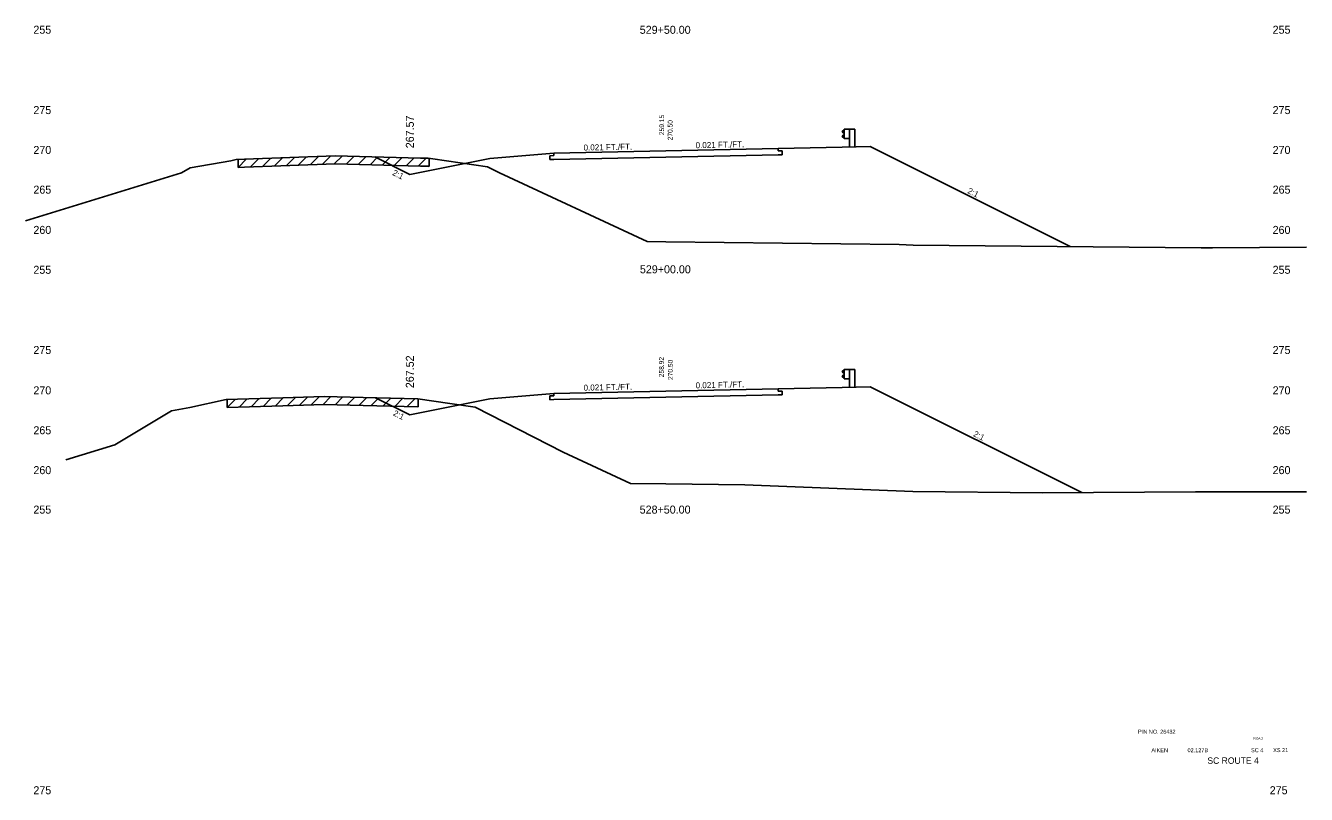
# Model space of a CAD drawing. Extents: x 883 to 1160, y 1002 to 4323.
# Drawn here: x 1000 to 1160, y 3395.1 to 3491.2 of the extents above; entities that cross this region are included whole.
import ezdxf

# ---------------------------------------------------------------- set-up
doc = ezdxf.new("R2010")
doc.units = 0
for name, color, linetype in [('Level 1', 7, 'Continuous'), ('Level 10', 7, 'Continuous'), ('Level 11', 7, 'Continuous'), ('Level 12', 7, 'Continuous'), ('Level 24', 7, 'Continuous'), ('Level 3', 7, 'Continuous'), ('Level 32', 7, 'Continuous'), ('Level 33', 7, 'Continuous'), ('Level 59', 7, 'Continuous'), ('Level 6', 7, 'Continuous'), ('Level 60', 7, 'Continuous'), ('Level 61', 7, 'Continuous'), ('Level 7', 7, 'Continuous')]:
    doc.layers.add(name, color=color, linetype=linetype)

msp = doc.modelspace()

# ---------------------------------------------------------------- linework, layer by layer
at = {"layer": 'Level 11'}
for p, q in [((1066, 3475.21), (1066, 3474.91)), ((1094, 3475.49), (1094, 3475.79)), ((1094.5, 3475.5), (1094, 3475.49)), ((1094.5, 3475.02), (1094.5, 3475.5)), ((1066, 3474.91), (1065.5, 3474.9)), ((1065.5, 3474.9), (1065.5, 3474.42)), ((1065.5, 3474.42), (1066, 3474.43)), ((1094, 3475.01), (1094.5, 3475.02)), ((1066, 3444.91), (1065.5, 3444.9)), ((1065.5, 3444.9), (1065.5, 3444.42)), ((1066, 3445.21), (1066, 3444.91)), ((1094, 3445.49), (1094, 3445.79)), ((1094.5, 3445.5), (1094, 3445.49)), ((1094, 3445.01), (1094.5, 3445.02)), ((1094.5, 3445.02), (1094.5, 3445.5)), ((1065.5, 3444.42), (1066, 3444.43))]:
    msp.add_line(p, q, dxfattribs=at)
at = {"layer": 'Level 12'}
for p, q in [((1080, 3474.72), (1066, 3474.43)), ((1094, 3475.01), (1080, 3474.72)), ((1094, 3445.01), (1080, 3444.72)), ((1080, 3444.72), (1066, 3444.43))]:
    msp.add_line(p, q, dxfattribs=at)
at = {"layer": 'Level 24'}
for p, q in [((1102.27, 3478.13), (1102, 3477.93)), ((1102, 3477.93), (1102, 3477.88)), ((1102, 3477.88), (1102.27, 3477.68)), ((1102, 3477.36), (1102.27, 3477.56)), ((1102, 3477.31), (1102, 3477.36)), ((1102.27, 3477.11), (1102, 3477.31)), ((1102.27, 3477.04), (1102.27, 3478.21)), ((1102.27, 3478.21), (1102.94, 3478.21)), ((1102.27, 3477.04), (1102.94, 3477.04)), ((1102.94, 3478.21), (1102.94, 3475.98)), ((1102.94, 3478.21), (1103.6, 3478.21)), ((1103.6, 3478.21), (1103.6, 3475.99)), ((1102.27, 3448.13), (1102, 3447.93)), ((1102.27, 3447.04), (1102.27, 3448.21)), ((1102.27, 3448.21), (1102.94, 3448.21)), ((1102.94, 3448.21), (1102.94, 3445.98)), ((1102.94, 3448.21), (1103.6, 3448.21)), ((1103.6, 3448.21), (1103.6, 3445.99)), ((1102, 3447.93), (1102, 3447.88)), ((1102, 3447.88), (1102.27, 3447.68)), ((1102, 3447.36), (1102.27, 3447.56)), ((1102, 3447.31), (1102, 3447.36)), ((1102.27, 3447.11), (1102, 3447.31)), ((1102.27, 3447.04), (1102.94, 3447.04))]:
    msp.add_line(p, q, dxfattribs=at)
at = {"layer": 'Level 59'}
for p, q in [((1066, 3475.21), (1080, 3475.5)), ((1080, 3475.5), (1094, 3475.79)), ((1066, 3445.21), (1080, 3445.5)), ((1080, 3445.5), (1094, 3445.79))]:
    msp.add_line(p, q, dxfattribs=at)
at = {"layer": 'Level 6'}
for p, q in [((1058, 3474.54), (1066, 3475.21)), ((1094, 3475.79), (1102, 3475.96)), ((1102, 3475.96), (1105.5, 3476.03)), ((1058, 3444.54), (1066, 3445.21)), ((1094, 3445.79), (1102, 3445.96)), ((1102, 3445.96), (1105.5, 3446.03))]:
    msp.add_line(p, q, dxfattribs=at)
at = {"layer": 'Level 60'}
for p, q in [((1020.56, 3473.4), (1025.63, 3474.28)), ((1025.63, 3474.28), (1026.3, 3474.42)), ((1026.3, 3474.42), (1027.35, 3474.45)), ((1027.35, 3474.45), (1038.67, 3474.87)), ((1038.67, 3474.87), (1049.34, 3474.61)), ((1049.34, 3474.61), (1050.29, 3474.58)), ((1050.29, 3474.58), (1050.86, 3474.5)), ((1050.86, 3474.5), (1057.71, 3473.51)), ((1000, 3466.75), (1019.46, 3472.74)), ((1019.46, 3472.74), (1020.56, 3473.4)), ((1057.71, 3473.51), (1059.19, 3472.76)), ((1059.19, 3472.76), (1077.65, 3464.18)), ((1077.65, 3464.18), (1080, 3464.15)), ((1080, 3464.15), (1109.11, 3463.81)), ((1109.11, 3463.81), (1110.87, 3463.74)), ((1110.87, 3463.74), (1146.86, 3463.38)), ((1146.86, 3463.38), (1147.74, 3463.39)), ((1147.74, 3463.39), (1148.26, 3463.39)), ((1148.26, 3463.39), (1160, 3463.46)), ((1032.14, 3444.64), (1037.31, 3444.83)), ((1037.31, 3444.83), (1042.18, 3444.71)), ((1018.22, 3443.04), (1020.51, 3443.44)), ((1020.51, 3443.44), (1025.07, 3444.43)), ((1025.07, 3444.43), (1032.14, 3444.64)), ((1042.18, 3444.71), (1048.98, 3444.54)), ((1048.98, 3444.54), (1053.01, 3443.96)), ((1053.01, 3443.96), (1056.15, 3443.5)), ((1056.15, 3443.5), (1067.15, 3437.88)), ((1011.14, 3438.8), (1018.22, 3443.04)), ((1005.03, 3436.92), (1011.14, 3438.8)), ((1067.15, 3437.88), (1075.57, 3433.97)), ((1075.57, 3433.97), (1080, 3433.92)), ((1080, 3433.92), (1089.85, 3433.8)), ((1089.85, 3433.8), (1110.85, 3432.95)), ((1110.85, 3432.95), (1127.05, 3432.79)), ((1127.05, 3432.79), (1146.13, 3432.9)), ((1146.13, 3432.9), (1157.43, 3432.9)), ((1157.43, 3432.9), (1160, 3432.91))]:
    msp.add_line(p, q, dxfattribs=at)
at = {"layer": 'Level 61'}
for p, q in [((1027.57, 3474.46), (1026.54, 3473.43)), ((1026.54, 3474.43), (1026.54, 3473.43)), ((1027.35, 3473.45), (1038.67, 3473.87)), ((1029.08, 3474.52), (1028.04, 3473.48)), ((1030.58, 3474.57), (1029.54, 3473.53)), ((1032.08, 3474.63), (1031.04, 3473.59)), ((1033.58, 3474.68), (1032.54, 3473.64)), ((1035.08, 3474.74), (1034.04, 3473.7)), ((1036.58, 3474.79), (1035.55, 3473.76)), ((1038.09, 3474.85), (1037.05, 3473.81)), ((1039.53, 3474.85), (1038.55, 3473.87)), ((1038.67, 3473.87), (1049.34, 3473.61)), ((1041.02, 3474.81), (1040.05, 3473.84)), ((1042.52, 3474.78), (1041.55, 3473.8)), ((1044.02, 3474.74), (1043.05, 3473.76)), ((1045.53, 3474.7), (1044.55, 3473.73)), ((1047.03, 3474.66), (1046.05, 3473.69)), ((1048.53, 3474.63), (1047.55, 3473.65)), ((1050.03, 3474.59), (1049.05, 3473.61)), ((1049.34, 3473.61), (1050.29, 3473.58)), ((1050.4, 3473.57), (1050.4, 3474.57)), ((1026.54, 3473.43), (1027.35, 3473.45)), ((1050.29, 3473.58), (1050.4, 3473.57)), ((1036.7, 3444.81), (1035.66, 3443.77)), ((1038.15, 3444.81), (1037.17, 3443.82)), ((1026.19, 3444.46), (1025.16, 3443.43)), ((1025.16, 3444.43), (1025.16, 3443.43)), ((1025.16, 3443.43), (1032.14, 3443.64)), ((1027.69, 3444.51), (1026.66, 3443.48)), ((1029.19, 3444.55), (1028.16, 3443.52)), ((1030.69, 3444.59), (1029.66, 3443.56)), ((1032.19, 3444.64), (1031.16, 3443.61)), ((1032.14, 3443.64), (1037.31, 3443.83)), ((1033.7, 3444.69), (1032.66, 3443.66)), ((1035.2, 3444.75), (1034.16, 3443.71)), ((1037.31, 3443.83), (1042.18, 3443.71)), ((1039.64, 3444.77), (1038.67, 3443.79)), ((1041.14, 3444.73), (1040.17, 3443.76)), ((1042.64, 3444.7), (1041.67, 3443.72)), ((1042.18, 3443.71), (1048.98, 3443.54)), ((1044.14, 3444.66), (1043.17, 3443.68)), ((1045.64, 3444.62), (1044.67, 3443.65)), ((1047.14, 3444.59), (1046.17, 3443.61)), ((1048.65, 3444.55), (1047.67, 3443.58)), ((1048.98, 3443.54), (1049.02, 3443.54)), ((1049.02, 3443.54), (1049.02, 3444.54))]:
    msp.add_line(p, q, dxfattribs=at)
at = {"layer": 'Level 7'}
for p, q in [((1105.5, 3476.03), (1130.47, 3463.54)), ((1043.63, 3474.75), (1048, 3472.57)), ((1048, 3472.57), (1058, 3474.54)), ((1105.5, 3446.03), (1131.93, 3432.82)), ((1043.69, 3444.67), (1048, 3442.52)), ((1048, 3442.52), (1058, 3444.54))]:
    msp.add_line(p, q, dxfattribs=at)

# ---------------------------------------------------------------- texts
at = {"layer": 'Level 1'}
for s, height, p in [('529+50.00', 1, (1076.72, 3490.13)), ('529+00.00', 1, (1076.74, 3460.21)), ('528+50.00', 1, (1076.71, 3430.19)), ('PIN NO. 26432', 0.5, (1138.97, 3402.69)), ('AIKEN', 0.5, (1140.64, 3400.38)), ('02.127B', 0.5, (1145.15, 3400.38)), ('SC 4', 0.5, (1153.09, 3400.38)), ('XS 21', 0.5, (1155.85, 3400.39)), ('SC ROUTE 4', 0.8, (1147.63, 3398.93))]:
    msp.add_text(s, height=height, dxfattribs=at).set_placement(p)
at = {"layer": 'Level 10'}
for s, p in [('259.15', (1079.76, 3477.47)), ('258.92', (1079.73, 3447.23))]:
    msp.add_text(s, height=0.6, rotation=90, dxfattribs=at).set_placement(p)
at = {"layer": 'Level 3'}
for s, height, p in [(' 255', 1, (1000.6, 3490.14)), (' 255', 1, (1155.41, 3490.14)), (' 275', 1, (1000.6, 3480.1)), (' 275', 1, (1155.41, 3480.1)), (' 270', 1, (1000.6, 3475.12)), (' 270', 1, (1155.41, 3475.12)), (' 265', 1, (1000.6, 3470.16)), (' 265', 1, (1155.41, 3470.16)), (' 260', 1, (1000.6, 3465.13)), (' 260', 1, (1155.41, 3465.13)), (' 255', 1, (1000.6, 3460.15)), (' 255', 1, (1155.41, 3460.15)), (' 275', 1, (1000.6, 3450.13)), (' 275', 1, (1155.41, 3450.13)), (' 270', 1, (1000.6, 3445.09)), (' 270', 1, (1155.41, 3445.09)), (' 265', 1, (1000.6, 3440.1)), (' 265', 1, (1155.41, 3440.1)), (' 260', 1, (1000.6, 3435.12)), (' 260', 1, (1155.41, 3435.12)), (' 255', 1, (1000.6, 3430.19)), (' 255', 1, (1155.41, 3430.19)), ('ROAD', 0.3, (1153.38, 3401.96)), (' 275', 1, (1000.6, 3395.13)), (' 275', 1, (1155.05, 3395.13))]:
    msp.add_text(s, height=height, dxfattribs=at).set_placement(p)
at = {"layer": 'Level 32'}
for s, rotation, p in [('0.021 FT./FT.', 1.1916, (1069.71, 3475.54)), ('0.021 FT./FT.', 1.1916, (1083.71, 3475.83)), ('2:1', 333.435, (1045.75, 3472.53)), ('2:1', 333.435, (1117.59, 3470.26)), ('0.021 FT./FT.', 1.1916, (1069.71, 3445.54)), ('0.021 FT./FT.', 1.1916, (1083.71, 3445.83)), ('2:1', 333.435, (1045.83, 3442.49)), ('2:1', 333.435, (1118.32, 3439.9))]:
    msp.add_text(s, height=0.75, rotation=rotation, dxfattribs=at).set_placement(p)
at = {"layer": 'Level 33'}
for s, p in [('267.57', (1048.5, 3475.83)), ('267.52', (1048.5, 3445.86))]:
    msp.add_text(s, height=1, rotation=90, dxfattribs=at).set_placement(p)
at = {"layer": 'Level 59'}
for p in [(1080.82, 3476.59), (1080.85, 3446.65)]:
    msp.add_text(' 270.50', height=0.6, rotation=90, dxfattribs=at).set_placement(p)

doc.saveas('drawing.dxf')
